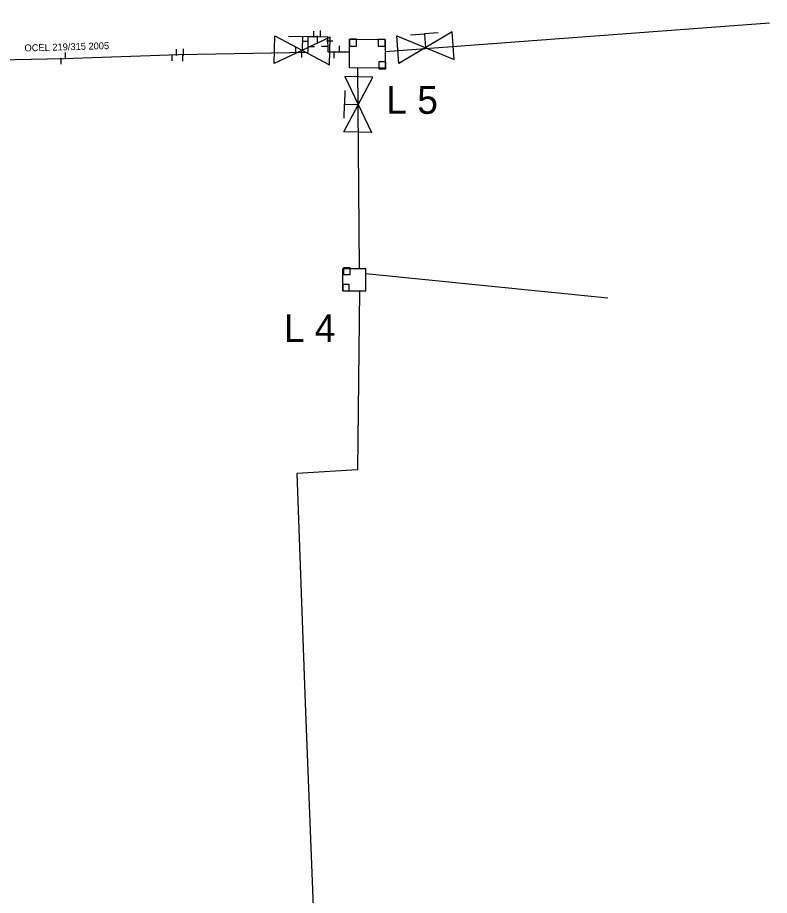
# Model space of a CAD drawing. Extents: x -642943 to -623314, y -1138561 to -1113539.
# Drawn here: x -641631.3 to -641550, y -1114309.7 to -1114214.8 of the extents above; entities that cross this region are included whole.
import ezdxf

# ---------------------------------------------------------------- set-up
doc = ezdxf.new("R2010")
doc.units = 0
for name, color, linetype in [('horkovod armatury', 7, 'Continuous'), ('horkovod dimenze', 7, 'Continuous'), ('horkovod předisol', 7, 'Continuous'), ('horkovod sváry', 7, 'Continuous'), ('horkovod trasa', 7, 'Continuous'), ('horkovod zrušený', 7, 'Continuous'), ('horkovod číslo šachty', 7, 'Continuous'), ('horkovod šachty', 7, 'Continuous')]:
    doc.layers.add(name, color=color, linetype=linetype)

# ---------------------------------------------------------------- blocks, each defined once
blk = doc.blocks.new('SPH')
at = {"layer": 'horkovod sváry'}
blk.add_line((0, -0.035), (0, 0.035), dxfattribs=at)
blk = doc.blocks.new('SCH_01_90')
at = {"layer": 'horkovod armatury'}
for p, q in [((10, 5), (-10, -5)), ((-10, -5), (-10, 5)), ((-10, 5), (10, -5)), ((-5, 5), (0, 5)), ((0, 5), (0, 0)), ((5, 5), (0, 5)), ((10, -5), (10, 5))]:
    blk.add_line(p, q, dxfattribs=at)
blk = doc.blocks.new('POINT_DISPLAY')
blk.add_line((0, 0), (0, 0))

msp = doc.modelspace()

# ---------------------------------------------------------------- linework, layer by layer
at = {"layer": 'horkovod předisol'}
msp.add_lwpolyline([(-641664.474, -1114214.815), (-641664.214, -1114220.358), (-641651.334, -1114219.945), (-641638.612, -1114219.504), (-641626.285, -1114219.23), (-641613.816, -1114218.821), (-641599.854, -1114218.558), (-641599.844, -1114216.89), (-641597.768, -1114216.852), (-641597.731, -1114218.521), (-641595.376, -1114218.511)], dxfattribs=at)
at = {"layer": 'horkovod trasa'}
for p, q in [((-641591.531, -1114218.475), (-641549.984, -1114215.389)), ((-641594.316, -1114241.98), (-641594.471, -1114220.267)), ((-641594.316, -1114244.38), (-641594.505, -1114263.724)), ((-641594.505, -1114263.724), (-641601.078, -1114264.103))]:
    msp.add_line(p, q, dxfattribs=at)
for points in [[(-641664.474, -1114214.815), (-641664.214, -1114220.358), (-641651.334, -1114219.945), (-641638.612, -1114219.504), (-641626.285, -1114219.23), (-641613.816, -1114218.821), (-641599.854, -1114218.558), (-641599.844, -1114216.89), (-641597.768, -1114216.852), (-641597.731, -1114218.521), (-641595.376, -1114218.511)], [(-641601.078, -1114264.103), (-641600.19, -1114288.954), (-641599.205, -1114313.772)]]:
    msp.add_lwpolyline(points, dxfattribs=at)
at = {"layer": 'horkovod zrušený'}
msp.add_line((-641593.614, -1114242.48), (-641567.442, -1114245.14), dxfattribs=at)
at = {"layer": 'horkovod šachty'}
for p, q in [((-641595.373, -1114217.165), (-641595.373, -1114217.915)), ((-641594.623, -1114217.165), (-641595.373, -1114217.165)), ((-641594.623, -1114217.915), (-641594.623, -1114217.165)), ((-641592.283, -1114217.175), (-641592.283, -1114217.925)), ((-641591.533, -1114217.175), (-641592.283, -1114217.175)), ((-641591.533, -1114217.925), (-641591.533, -1114217.175)), ((-641595.373, -1114217.915), (-641594.623, -1114217.915)), ((-641592.283, -1114217.925), (-641591.533, -1114217.925)), ((-641592.203, -1114219.615), (-641592.203, -1114220.365)), ((-641591.453, -1114219.615), (-641592.203, -1114219.615)), ((-641591.453, -1114220.365), (-641591.453, -1114219.615)), ((-641592.203, -1114220.365), (-641591.453, -1114220.365)), ((-641596.028, -1114241.89), (-641596.028, -1114242.59)), ((-641595.328, -1114241.89), (-641596.028, -1114241.89)), ((-641595.328, -1114242.59), (-641595.328, -1114241.89)), ((-641596.028, -1114242.59), (-641595.328, -1114242.59)), ((-641596.118, -1114243.68), (-641596.118, -1114244.38)), ((-641595.418, -1114243.68), (-641596.118, -1114243.68)), ((-641595.418, -1114244.38), (-641595.418, -1114243.68)), ((-641596.118, -1114244.38), (-641595.418, -1114244.38))]:
    msp.add_line(p, q, dxfattribs=at)
for points in [[(-641595.378, -1114220.265), (-641595.378, -1114217.165), (-641591.538, -1114217.175), (-641591.538, -1114220.275), (-641595.378, -1114220.265)], [(-641593.623, -1114244.38), (-641593.623, -1114241.98), (-641596.123, -1114241.98), (-641596.123, -1114244.38), (-641593.623, -1114244.38)]]:
    msp.add_lwpolyline(points, dxfattribs=at)

# ---------------------------------------------------------------- block references
at = {"layer": 'horkovod armatury', "xscale": 0.30000998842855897}
for p, yscale, rotation in [((-641600.496, -1114218.354), 0.30000998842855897, -1.2985175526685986), ((-641587.177, -1114218.072), 0.300009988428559, 4.174035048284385), ((-641594.439, -1114224.224), 0.30000998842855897, 88.70148244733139)]:
    msp.add_blockref('SCH_01_90', p, dxfattribs=dict(at, yscale=yscale, rotation=rotation))
at = {"layer": 'horkovod sváry', "xscale": 10, "yscale": 10}
for p in [(-641599.239, -1114216.62), (-641598.529, -1114216.55), (-641598.859, -1114217.14), (-641614.079, -1114218.57), (-641613.339, -1114218.557), (-641601.179, -1114218.34), (-641596.459, -1114218.24), (-641626.549, -1114219.52), (-641626.079, -1114218.96), (-641614.549, -1114219.16), (-641613.399, -1114219.19), (-641600.529, -1114218.8), (-641597.039, -1114218.84)]:
    msp.add_blockref('SPH', p, dxfattribs=at)
at = {"layer": 'horkovod sváry'}
for p, xscale, yscale, rotation in [((-641600.179, -1114217.37), 10.000016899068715, 10.000016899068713, -89.19182307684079), ((-641599.519, -1114217.94), 10.000004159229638, 10.000004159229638, -89.36739342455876), ((-641598.069, -1114217.91), 10.000020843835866, 10.00002084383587, -89.19022241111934), ((-641597.519, -1114217.32), 9.999989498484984, 9.999989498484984, -89.76707859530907)]:
    msp.add_blockref('SPH', p, dxfattribs=dict(at, xscale=xscale, yscale=yscale, rotation=rotation))
at = {"layer": 'horkovod šachty'}
for p in [(-641594.998, -1114217.54), (-641591.908, -1114217.55), (-641591.828, -1114219.99), (-641595.678, -1114242.24), (-641595.768, -1114244.03)]:
    msp.add_blockref('POINT_DISPLAY', p, dxfattribs=at)

# ---------------------------------------------------------------- texts
at = {"layer": 'horkovod dimenze'}
msp.add_text('OCEL 219/315 2005', height=0.75, rotation=1.63658, dxfattribs=at).set_placement((-641630.505, -1114218.482))
at = {"layer": 'horkovod číslo šachty'}
for s, p in [('L 5', (-641591.403, -1114225.225)), ('L 4', (-641602.479, -1114249.895))]:
    msp.add_text(s, height=3, dxfattribs=at).set_placement(p)

doc.saveas('drawing.dxf')
